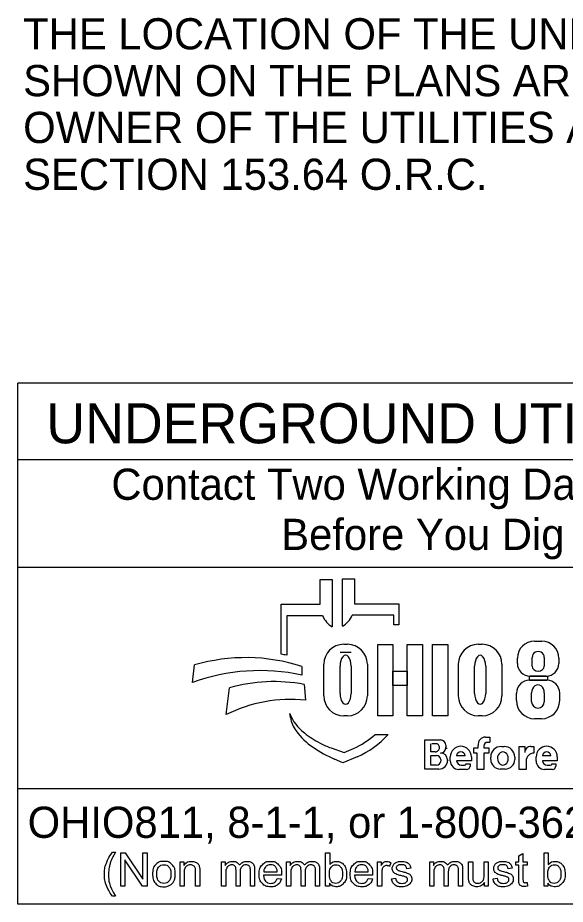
# Model space of a CAD drawing. Extents: x 0 to 34, y -5.8 to 22.
# Drawn here: x 4.602 to 7.056, y 9.052 to 13.029 of the extents above; entities that cross this region are included whole.
import ezdxf

# ---------------------------------------------------------------- set-up
doc = ezdxf.new("R2010")
doc.units = 0
doc.layers.add('SH_Data', color=7, linetype='Continuous')
doc.layers.add('SH_Text', color=7, linetype='Continuous')

msp = doc.modelspace()

# ---------------------------------------------------------------- linework, layer by layer
at = {"layer": 'SH_Data'}
for p, q in [((4.602, 9.0516), (4.602, 11.3891)), ((8.852, 11.3891), (4.602, 11.3891)), ((4.602, 11.0476), (8.852, 11.0476)), ((4.602, 10.5642), (8.852, 10.5642)), ((8.852, 9.5695), (4.602, 9.5695)), ((8.852, 9.0516), (4.602, 9.0516))]:
    msp.add_line(p, q, dxfattribs=at)
at = {"layer": 'SH_Text'}
for p, q in [((5.958, 10.3972), (5.958, 10.5086)), ((5.958, 10.5086), (6.0116, 10.5086)), ((6.0116, 10.5086), (6.0116, 10.2966)), ((6.0573, 10.2989), (6.0573, 10.511)), ((6.0573, 10.511), (6.1109, 10.511)), ((6.1109, 10.511), (6.1109, 10.3995)), ((5.782, 10.1733), (5.782, 10.3972)), ((5.782, 10.3972), (5.958, 10.3972)), ((6.1109, 10.3995), (6.3102, 10.3995)), ((6.3102, 10.3995), (6.3102, 10.3057)), ((5.8073, 10.3457), (5.8073, 10.1689)), ((5.9684, 10.3457), (5.8073, 10.3457)), ((6.2869, 10.348), (6.1005, 10.348)), ((6.2869, 10.3057), (6.2869, 10.348)), ((6.3102, 10.3057), (6.2869, 10.3057)), ((6.9176, 10.232), (6.9503, 10.232)), ((6.063, 10.218), (6.0795, 10.218)), ((6.666, 10.218), (6.6826, 10.218)), ((6.0962, 10.181), (6.0464, 10.181)), ((6.8412, 10.1314), (6.8412, 10.1557)), ((6.9074, 10.12), (6.9074, 10.1593)), ((6.9616, 10.1593), (6.9616, 10.12)), ((7.0266, 10.1557), (7.0266, 10.1314)), ((5.3847, 10.047), (5.3941, 10.1251)), ((5.8753, 10.1186), (5.8753, 10.0798)), ((5.9735, 9.9865), (5.9735, 10.1285)), ((6.0464, 9.9979), (6.0464, 10.1202)), ((6.0962, 10.1202), (6.0962, 9.9979)), ((6.169, 10.1285), (6.169, 9.9865)), ((6.5766, 9.9865), (6.5766, 10.1285)), ((6.6495, 9.9979), (6.6495, 10.1202)), ((6.6993, 10.1202), (6.6993, 9.9979)), ((6.772, 10.1285), (6.772, 9.9865)), ((6.9706, 10.0754), (6.8972, 10.0754)), ((5.5365, 9.9024), (5.5512, 10.0226)), ((5.8853, 10.038), (5.8915, 9.967)), ((6.8954, 10.0571), (6.9728, 10.0571)), ((6.8375, 9.9651), (6.8375, 9.9992)), ((6.905, 9.9592), (6.905, 10.0001)), ((6.9619, 10.0001), (6.9619, 9.9592)), ((7.0306, 9.9992), (7.0306, 9.9651)), ((5.8242, 9.8895), (5.8211, 9.9075)), ((6.0795, 9.897), (6.063, 9.897)), ((6.6826, 9.897), (6.666, 9.897)), ((6.9497, 9.8842), (6.9185, 9.8842)), ((6.2045, 9.8137), (6.2619, 9.8137)), ((6.4258, 9.6579), (6.4258, 9.7886)), ((6.4258, 9.7886), (6.4969, 9.7886)), ((6.6983, 9.8014), (6.7178, 9.8014)), ((6.7178, 9.8014), (6.7178, 9.7784)), ((6.006, 9.7533), (6.0655, 9.7328)), ((6.0655, 9.7328), (6.1065, 9.7506)), ((6.4537, 9.7352), (6.4537, 9.7721)), ((6.4789, 9.7721), (6.4577, 9.7721)), ((6.5207, 9.7649), (6.5207, 9.757)), ((6.6458, 9.7301), (6.6458, 9.753)), ((6.6458, 9.753), (6.6651, 9.753)), ((6.6651, 9.753), (6.6651, 9.7635)), ((6.6912, 9.7615), (6.6912, 9.753)), ((6.6912, 9.753), (6.7127, 9.753)), ((6.7178, 9.778), (6.7077, 9.778)), ((6.7127, 9.753), (6.7127, 9.7301)), ((6.7696, 9.7596), (6.7817, 9.7596)), ((6.8498, 9.6567), (6.8498, 9.7594)), ((6.8498, 9.7594), (6.8744, 9.7594)), ((6.8744, 9.7594), (6.8744, 9.7325)), ((6.9016, 9.7594), (6.9155, 9.7594)), ((6.9155, 9.7594), (6.9155, 9.7297)), ((6.1227, 9.7132), (6.0594, 9.6858)), ((6.4732, 9.7352), (6.4537, 9.7352)), ((6.4537, 9.6757), (6.4537, 9.7186)), ((6.4537, 9.7186), (6.4793, 9.7186)), ((6.5403, 9.6947), (6.5403, 9.7131)), ((6.6069, 9.7171), (6.5684, 9.7171)), ((6.6348, 9.7131), (6.6348, 9.6954)), ((6.6607, 9.7301), (6.6458, 9.7301)), ((6.6607, 9.6567), (6.6607, 9.7301)), ((6.7127, 9.7301), (6.6912, 9.7301)), ((6.6912, 9.7301), (6.6912, 9.6567)), ((6.7218, 9.701), (6.7218, 9.7118)), ((6.8295, 9.7118), (6.8295, 9.701)), ((6.9252, 9.6947), (6.9252, 9.7131)), ((6.9918, 9.7171), (6.9533, 9.7171)), ((7.0198, 9.7131), (7.0198, 9.6954)), ((6.0594, 9.6858), (6.0221, 9.7022)), ((6.479, 9.6757), (6.4537, 9.6757)), ((6.4974, 9.7005), (6.4974, 9.6941)), ((6.5288, 9.6976), (6.5288, 9.6972)), ((6.6348, 9.6954), (6.5684, 9.6954)), ((6.5894, 9.6762), (6.6035, 9.6762)), ((6.612, 9.6818), (6.6289, 9.6818)), ((6.6289, 9.6818), (6.6289, 9.6719)), ((6.8803, 9.6948), (6.8803, 9.6567)), ((7.0198, 9.6954), (6.9533, 9.6954)), ((6.9743, 9.6762), (6.9884, 9.6762)), ((6.997, 9.6818), (7.0138, 9.6818)), ((7.0138, 9.6818), (7.0138, 9.6719)), ((6.4894, 9.6579), (6.4258, 9.6579)), ((6.6137, 9.6567), (6.5783, 9.6567)), ((6.6912, 9.6567), (6.6607, 9.6567)), ((6.7867, 9.6582), (6.7645, 9.6582)), ((6.8803, 9.6567), (6.8498, 9.6567)), ((6.9986, 9.6567), (6.9632, 9.6567))]:
    msp.add_line(p, q, dxfattribs=at)
for points in [[(6.2154, 10.2169), (6.2834, 10.2169), (6.2834, 9.897), (6.2154, 9.897)], [(6.3476, 10.2169), (6.4155, 10.2169), (6.4155, 9.897), (6.3476, 9.897)], [(6.4609, 10.2169), (6.5296, 10.2169), (6.5296, 9.897), (6.4609, 9.897)], [(6.2834, 10.097), (6.3476, 10.097), (6.3476, 10.033), (6.2834, 10.033)], [(6.8951, 10.0754), (6.9768, 10.0754), (6.9768, 10.0569), (6.8951, 10.0569)]]:
    msp.add_lwpolyline(points, close=True, dxfattribs=at)
for points in [[(5.0266, 9.2854), (5.0397, 9.2854)], [(5.0633, 9.1328), (5.0633, 9.2829), (5.0836, 9.2829), (5.1627, 9.165), (5.1627, 9.2829), (5.1816, 9.2829), (5.1816, 9.1328), (5.1613, 9.1328), (5.0823, 9.2507), (5.0823, 9.1328), (5.0633, 9.1328)], [(5.9988, 9.1328), (5.9817, 9.1328), (5.9817, 9.2829), (6.0001, 9.2829), (6.0001, 9.2294)], [(6.8477, 9.1646), (6.8477, 9.2273), (6.8341, 9.2273), (6.8341, 9.2416), (6.8477, 9.2416), (6.8477, 9.2686), (6.8661, 9.2796), (6.8661, 9.2416), (6.8846, 9.2416), (6.8846, 9.2273), (6.8661, 9.2273), (6.8661, 9.1636)], [(6.9778, 9.1328), (6.9608, 9.1328), (6.9608, 9.2829), (6.9792, 9.2829), (6.9792, 9.2294)], [(5.3293, 9.1328), (5.3293, 9.2416), (5.3459, 9.2416), (5.3459, 9.2261)], [(5.5157, 9.1328), (5.5157, 9.2416), (5.5322, 9.2416), (5.5322, 9.2263)], [(5.8071, 9.1328), (5.8071, 9.2416), (5.8235, 9.2416), (5.8235, 9.2263)], [(6.2148, 9.1328), (6.2148, 9.2416), (6.2314, 9.2416), (6.2314, 9.2251)], [(6.2739, 9.2381), (6.2674, 9.2211)], [(6.4481, 9.1328), (6.4481, 9.2416), (6.4645, 9.2416), (6.4645, 9.2263)], [(6.6224, 9.1742), (6.6224, 9.2416), (6.6408, 9.2416), (6.6408, 9.1813)], [(6.6921, 9.1834), (6.6921, 9.2416), (6.7105, 9.2416), (6.7105, 9.1328), (6.694, 9.1328)], [(5.3477, 9.1922), (5.3477, 9.1328), (5.3293, 9.1328)], [(5.4176, 9.1997), (5.4176, 9.1328), (5.3992, 9.1328), (5.3992, 9.1989)], [(5.5341, 9.1892), (5.5341, 9.1328), (5.5157, 9.1328)], [(5.5988, 9.196), (5.5988, 9.1328), (5.5803, 9.1328), (5.5803, 9.2034)], [(5.6632, 9.2075), (5.6632, 9.1328), (5.6448, 9.1328), (5.6448, 9.2013)], [(5.7043, 9.1976), (5.7651, 9.1976)], [(5.8255, 9.1892), (5.8255, 9.1328), (5.8071, 9.1328)], [(5.8901, 9.196), (5.8901, 9.1328), (5.8717, 9.1328), (5.8717, 9.2034)], [(5.9546, 9.2075), (5.9546, 9.1328), (5.9362, 9.1328), (5.9362, 9.2013)], [(6.1123, 9.1976), (6.1731, 9.1976)], [(6.2333, 9.1898), (6.2333, 9.1328), (6.2148, 9.1328)], [(6.3639, 9.2135), (6.3458, 9.2111)], [(6.4665, 9.1892), (6.4665, 9.1328), (6.4481, 9.1328)], [(6.5311, 9.196), (6.5311, 9.1328), (6.5127, 9.1328), (6.5127, 9.2034)], [(6.5956, 9.2075), (6.5956, 9.1328), (6.5772, 9.1328), (6.5772, 9.2013)], [(6.8184, 9.2135), (6.8003, 9.2111)], [(5.7844, 9.1824), (5.7033, 9.1824)], [(5.7649, 9.1679), (5.7839, 9.1655)], [(6.1924, 9.1824), (6.1113, 9.1824)], [(6.1729, 9.1679), (6.1919, 9.1655)], [(6.2774, 9.1653), (6.2956, 9.1681)], [(6.694, 9.1328), (6.694, 9.1488)], [(6.732, 9.1653), (6.7502, 9.1681)], [(6.8846, 9.1492), (6.8872, 9.1329)], [(5.9988, 9.1464), (5.9988, 9.1328)], [(6.9778, 9.1464), (6.9778, 9.1328)], [(5.0397, 9.0886), (5.0266, 9.0886)]]:
    msp.add_lwpolyline(points, dxfattribs=at)
for centre, radius, start, end in [((6.0597, 10.3825), 0.0985, 201.9296, 240.7469), ((6.0092, 10.3848), 0.0985, 299.2531, 338.0704), ((6.9176, 10.1557), 0.0763, 90, 180), ((6.9503, 10.1557), 0.0763, 0, 90), ((6.063, 10.1285), 0.0895, 90, 180), ((6.0795, 10.1285), 0.0895, 0, 90), ((6.666, 10.1285), 0.0895, 90, 180), ((6.6826, 10.1285), 0.0895, 0, 90), ((5.6241, 9.339), 0.8191, 72.1402, 106.3144), ((5.6539, 9.3643), 0.8191, 79.2074, 81.0007), ((6.8972, 10.1314), 0.056, 180, 270), ((6.9706, 10.1314), 0.056, 270, 0), ((5.6872, 9.2079), 0.8919, 77.8238, 109.8274), ((5.7511, 9.3182), 0.7322, 79.44, 105.8467), ((6.8954, 9.9992), 0.0579, 90, 180), ((6.9728, 9.9992), 0.0579, 0, 90), ((6.063, 9.9865), 0.0895, 180, 270), ((6.0795, 9.9865), 0.0895, 270, 0), ((6.666, 9.9865), 0.0895, 180, 270), ((6.6826, 9.9865), 0.0895, 270, 0), ((5.8231, 9.335), 0.6357, 83.8248, 116.8021), ((6.9185, 9.9651), 0.081, 180, 270), ((6.9497, 9.9651), 0.081, 270, 0), ((6.0085, 9.9796), 0.2008, 201.0457, 232.5314), ((5.9655, 9.9136), 0.1433, 189.6817, 216.0884), ((6.0992, 10.0111), 0.3088, 216.0884, 235.7167), ((6.2011, 10.2308), 0.5173, 232.5314, 241.794), ((5.9631, 10.0811), 0.3602, 293.4582, 312.0712), ((5.9631, 10.0811), 0.401, 293.4582, 317.8286), ((6.4969, 9.7649), 0.0238, 0, 90), ((6.6983, 9.7679), 0.0335, 90, 187.5187), ((6.2657, 10.2553), 0.6044, 235.7167, 246.2325), ((6.1159, 10.072), 0.3371, 241.794, 250.9821), ((6.4732, 9.7539), 0.0187, 270, 2.0582), ((6.475, 9.7552), 0.0169, 357.8325, 90), ((6.4965, 9.7542), 0.0243, 270, 6.6529), ((6.5071, 9.7527), 0.0175, 347.4023, 0), ((6.5876, 9.7131), 0.0473, 0, 180), ((6.7077, 9.7615), 0.0165, 90, 180), ((6.7696, 9.7118), 0.0478, 90, 180), ((6.7817, 9.7118), 0.0478, 0, 90), ((6.9013, 9.7325), 0.0269, 89.2449, 180), ((6.9725, 9.7131), 0.0473, 0, 180), ((6.4793, 9.7005), 0.0181, 0, 90), ((6.4967, 9.6978), 0.0321, 4.0748, 90), ((6.4958, 9.6976), 0.033, 0, 11.7502), ((6.5876, 9.7161), 0.0193, 2.9632, 177.0368), ((6.9152, 9.6948), 0.0349, 89.6033, 180), ((6.9725, 9.7161), 0.0193, 2.9632, 177.0368), ((6.479, 9.6941), 0.0184, 270, 0), ((6.4894, 9.6972), 0.0393, 270, 0), ((6.5783, 9.6947), 0.038, 180, 270), ((6.5894, 9.6972), 0.021, 184.827, 270), ((6.6035, 9.6856), 0.00938, 270, 335.9979), ((6.6137, 9.6719), 0.0152, 270, 0), ((6.7645, 9.701), 0.0428, 180, 270), ((6.7867, 9.701), 0.0428, 270, 0), ((6.9632, 9.6947), 0.038, 180, 270), ((6.9743, 9.6972), 0.021, 184.827, 270), ((6.9884, 9.6856), 0.00938, 270, 335.9979), ((6.9986, 9.6719), 0.0152, 270, 0)]:
    msp.add_arc(centre, radius, start, end, dxfattribs=at)
for centre, major_axis, ratio, start_param, end_param in [((6.9345, 10.1593), (0.0271, 0), 0.969373, 0, 3.141593), ((6.0713, 10.1202), (0, 0.0484), 0.514403, 4.712389, 7.853982), ((6.6744, 10.1202), (0, 0.0484), 0.514403, 4.712389, 7.853982), ((6.9345, 10.12), (0.0271, 0), 0.818453, 3.141593, 6.283185), ((6.9335, 10.0001), (0, 0.0358), 0.794529, 4.712389, 7.853982), ((6.0713, 9.9979), (0, 0.0484), 0.514403, 1.570796, 4.712389), ((6.6744, 9.9979), (0, 0.0484), 0.514403, 1.570796, 4.712389), ((6.9335, 9.9592), (0.0284, 0), 0.959837, 3.141593, 6.283185), ((6.7761, 9.7064), (0, 0.029), 0.832186, 4.712389, 7.853982), ((6.7761, 9.7064), (0, 0.0302), 0.797287, 1.570796, 4.712389)]:
    msp.add_ellipse(centre, major_axis=major_axis, ratio=ratio, start_param=start_param, end_param=end_param, dxfattribs=at)
for points in [[(5.0266, 9.0886), (5.0113, 9.1079), (5.0007, 9.1337), (4.9902, 9.1595), (4.9902, 9.1871), (4.9902, 9.2115), (4.9981, 9.2338), (5.0073, 9.2597), (5.0266, 9.2854)], [(5.0397, 9.2854), (5.0274, 9.2641), (5.0234, 9.255), (5.0172, 9.2409), (5.0136, 9.2255), (5.0092, 9.2064), (5.0092, 9.187), (5.0092, 9.1378), (5.0397, 9.0886)], [(5.2058, 9.1872), (5.2058, 9.2174), (5.2226, 9.2319), (5.2366, 9.244), (5.2568, 9.244), (5.2792, 9.244), (5.2934, 9.2293), (5.3077, 9.2146), (5.3077, 9.1887), (5.3077, 9.1677), (5.3014, 9.1557), (5.2951, 9.1437), (5.283, 9.137), (5.271, 9.1304), (5.2568, 9.1304), (5.2339, 9.1304), (5.2199, 9.145), (5.2058, 9.1597), (5.2058, 9.1872)], [(5.2248, 9.1872), (5.2248, 9.1663), (5.2339, 9.1559), (5.243, 9.1455), (5.2568, 9.1455), (5.2705, 9.1455), (5.2796, 9.1559), (5.2887, 9.1664), (5.2887, 9.1878), (5.2887, 9.208), (5.2795, 9.2184), (5.2704, 9.2288), (5.2568, 9.2288), (5.243, 9.2288), (5.2339, 9.2184), (5.2248, 9.2081), (5.2248, 9.1872)], [(5.3459, 9.2261), (5.3579, 9.244), (5.3805, 9.244), (5.3903, 9.244), (5.3985, 9.2405), (5.4068, 9.237), (5.4109, 9.2312), (5.415, 9.2255), (5.4166, 9.2176), (5.4176, 9.2125), (5.4176, 9.1997)], [(5.3992, 9.1989), (5.3992, 9.2102), (5.3971, 9.2158), (5.3949, 9.2213), (5.3894, 9.2247), (5.384, 9.228), (5.3766, 9.228), (5.3648, 9.228), (5.3563, 9.2205), (5.3477, 9.2131), (5.3477, 9.1922)], [(5.5322, 9.2263), (5.5373, 9.2343), (5.5458, 9.2391), (5.5543, 9.244), (5.5652, 9.244), (5.5773, 9.244), (5.585, 9.239), (5.5927, 9.234), (5.5959, 9.2249), (5.6088, 9.244), (5.6296, 9.244), (5.6458, 9.244), (5.6545, 9.2351), (5.6632, 9.2261), (5.6632, 9.2075)], [(5.5803, 9.2034), (5.5803, 9.2157), (5.5758, 9.2219), (5.5713, 9.228), (5.5611, 9.228), (5.5533, 9.228), (5.5467, 9.2239), (5.5401, 9.2198), (5.5371, 9.2119), (5.5341, 9.204), (5.5341, 9.1892)], [(5.6448, 9.2013), (5.6448, 9.2123), (5.643, 9.2172), (5.6412, 9.2221), (5.6365, 9.225), (5.6318, 9.228), (5.6254, 9.228), (5.6139, 9.228), (5.6064, 9.2204), (5.5988, 9.2127), (5.5988, 9.196)], [(5.7839, 9.1655), (5.7794, 9.1488), (5.7672, 9.1396), (5.755, 9.1304), (5.7361, 9.1304), (5.7122, 9.1304), (5.6983, 9.1451), (5.6843, 9.1598), (5.6843, 9.1863), (5.6843, 9.2137), (5.6984, 9.2289), (5.7125, 9.244), (5.7351, 9.244), (5.7569, 9.244), (5.7707, 9.2292), (5.7845, 9.2143), (5.7845, 9.1874), (5.7845, 9.1857), (5.7844, 9.1824)], [(5.7651, 9.1976), (5.7639, 9.2113), (5.7581, 9.2182), (5.7493, 9.2289), (5.7353, 9.2289), (5.7226, 9.2289), (5.7139, 9.2204), (5.7052, 9.2118), (5.7043, 9.1976)], [(5.8235, 9.2263), (5.8287, 9.2343), (5.8372, 9.2391), (5.8457, 9.244), (5.8565, 9.244), (5.8686, 9.244), (5.8764, 9.239), (5.8841, 9.234), (5.8873, 9.2249), (5.9002, 9.244), (5.9209, 9.244), (5.9371, 9.244), (5.9459, 9.2351), (5.9546, 9.2261), (5.9546, 9.2075)], [(5.8717, 9.2034), (5.8717, 9.2157), (5.8672, 9.2219), (5.8627, 9.228), (5.8525, 9.228), (5.8447, 9.228), (5.838, 9.2239), (5.8314, 9.2198), (5.8285, 9.2119), (5.8255, 9.204), (5.8255, 9.1892)], [(5.9362, 9.2013), (5.9362, 9.2123), (5.9344, 9.2172), (5.9326, 9.2221), (5.9279, 9.225), (5.9231, 9.228), (5.9168, 9.228), (5.9053, 9.228), (5.8977, 9.2204), (5.8901, 9.2127), (5.8901, 9.196)], [(5.9985, 9.188), (5.9985, 9.1684), (6.0039, 9.1597), (6.0126, 9.1455), (6.0274, 9.1455), (6.0394, 9.1455), (6.0482, 9.156), (6.057, 9.1665), (6.057, 9.1873), (6.057, 9.2086), (6.0486, 9.2188), (6.0402, 9.2289), (6.0282, 9.2289), (6.0161, 9.2289), (6.0073, 9.2184), (5.9985, 9.2079), (5.9985, 9.188)], [(6.0001, 9.2294), (6.0118, 9.244), (6.0299, 9.244), (6.04, 9.244), (6.0489, 9.24), (6.0579, 9.2359), (6.0637, 9.2286), (6.0695, 9.2213), (6.0727, 9.211), (6.076, 9.2006), (6.076, 9.1888), (6.076, 9.1609), (6.0622, 9.1456), (6.0484, 9.1304), (6.029, 9.1304), (6.0097, 9.1304), (5.9988, 9.1464)], [(6.1919, 9.1655), (6.1874, 9.1488), (6.1752, 9.1396), (6.163, 9.1304), (6.1441, 9.1304), (6.1202, 9.1304), (6.1063, 9.1451), (6.0923, 9.1598), (6.0923, 9.1863), (6.0923, 9.2137), (6.1064, 9.2289), (6.1205, 9.244), (6.1431, 9.244), (6.1649, 9.244), (6.1787, 9.2292), (6.1925, 9.2143), (6.1925, 9.1874), (6.1925, 9.1857), (6.1924, 9.1824)], [(6.1731, 9.1976), (6.1718, 9.2113), (6.1661, 9.2182), (6.1573, 9.2289), (6.1433, 9.2289), (6.1305, 9.2289), (6.1219, 9.2204), (6.1132, 9.2118), (6.1123, 9.1976)], [(6.2314, 9.2251), (6.2378, 9.2367), (6.2432, 9.2403), (6.2485, 9.244), (6.255, 9.244), (6.2643, 9.244), (6.2739, 9.2381)], [(6.3458, 9.2111), (6.3445, 9.2195), (6.3386, 9.2242), (6.3327, 9.2289), (6.322, 9.2289), (6.3093, 9.2289), (6.3038, 9.2247), (6.2984, 9.2205), (6.2984, 9.2149), (6.2984, 9.2113), (6.3006, 9.2084), (6.3029, 9.2054), (6.3077, 9.2035), (6.3105, 9.2024), (6.324, 9.1987), (6.3436, 9.1935), (6.3514, 9.1902), (6.3591, 9.1869), (6.3636, 9.1805), (6.368, 9.1742), (6.368, 9.1648), (6.368, 9.1556), (6.3626, 9.1474), (6.3572, 9.1393), (6.347, 9.1348), (6.3369, 9.1304), (6.324, 9.1304), (6.3028, 9.1304), (6.2917, 9.1392), (6.2805, 9.148), (6.2774, 9.1653)], [(6.2956, 9.1681), (6.2972, 9.1572), (6.3042, 9.1513), (6.3113, 9.1455), (6.3239, 9.1455), (6.3366, 9.1455), (6.3428, 9.1507), (6.349, 9.1558), (6.349, 9.1628), (6.349, 9.1691), (6.3435, 9.1727), (6.3397, 9.1751), (6.3246, 9.1789), (6.3043, 9.184), (6.2965, 9.1878), (6.2886, 9.1915), (6.2846, 9.1981), (6.2805, 9.2047), (6.2805, 9.2127), (6.2805, 9.22), (6.2839, 9.2262), (6.2872, 9.2324), (6.293, 9.2364), (6.2973, 9.2396), (6.3047, 9.2418), (6.3121, 9.244), (6.3207, 9.244), (6.3335, 9.244), (6.3432, 9.2403), (6.3529, 9.2366), (6.3575, 9.2303), (6.3621, 9.224), (6.3639, 9.2135)], [(6.4645, 9.2263), (6.4697, 9.2343), (6.4782, 9.2391), (6.4867, 9.244), (6.4975, 9.244), (6.5096, 9.244), (6.5174, 9.239), (6.5251, 9.234), (6.5283, 9.2249), (6.5412, 9.244), (6.5619, 9.244), (6.5781, 9.244), (6.5869, 9.2351), (6.5956, 9.2261), (6.5956, 9.2075)], [(6.5127, 9.2034), (6.5127, 9.2157), (6.5082, 9.2219), (6.5037, 9.228), (6.4934, 9.228), (6.4857, 9.228), (6.479, 9.2239), (6.4724, 9.2198), (6.4695, 9.2119), (6.4665, 9.204), (6.4665, 9.1892)], [(6.5772, 9.2013), (6.5772, 9.2123), (6.5754, 9.2172), (6.5736, 9.2221), (6.5689, 9.225), (6.5641, 9.228), (6.5578, 9.228), (6.5463, 9.228), (6.5387, 9.2204), (6.5311, 9.2127), (6.5311, 9.196)], [(6.8003, 9.2111), (6.7991, 9.2195), (6.7932, 9.2242), (6.7873, 9.2289), (6.7765, 9.2289), (6.7638, 9.2289), (6.7584, 9.2247), (6.753, 9.2205), (6.753, 9.2149), (6.753, 9.2113), (6.7552, 9.2084), (6.7575, 9.2054), (6.7623, 9.2035), (6.7651, 9.2024), (6.7786, 9.1987), (6.7982, 9.1935), (6.8059, 9.1902), (6.8137, 9.1869), (6.8181, 9.1805), (6.8225, 9.1742), (6.8225, 9.1648), (6.8225, 9.1556), (6.8172, 9.1474), (6.8118, 9.1393), (6.8016, 9.1348), (6.7914, 9.1304), (6.7786, 9.1304), (6.7574, 9.1304), (6.7462, 9.1392), (6.7351, 9.148), (6.732, 9.1653)], [(6.7502, 9.1681), (6.7518, 9.1572), (6.7588, 9.1513), (6.7658, 9.1455), (6.7785, 9.1455), (6.7912, 9.1455), (6.7974, 9.1507), (6.8035, 9.1558), (6.8035, 9.1628), (6.8035, 9.1691), (6.7981, 9.1727), (6.7943, 9.1751), (6.7792, 9.1789), (6.7589, 9.184), (6.7511, 9.1878), (6.7432, 9.1915), (6.7392, 9.1981), (6.7351, 9.2047), (6.7351, 9.2127), (6.7351, 9.22), (6.7384, 9.2262), (6.7418, 9.2324), (6.7475, 9.2364), (6.7518, 9.2396), (6.7593, 9.2418), (6.7667, 9.244), (6.7752, 9.244), (6.788, 9.244), (6.7977, 9.2403), (6.8074, 9.2366), (6.8121, 9.2303), (6.8167, 9.224), (6.8184, 9.2135)], [(6.9776, 9.188), (6.9776, 9.1684), (6.9829, 9.1597), (6.9916, 9.1455), (7.0064, 9.1455), (7.0185, 9.1455), (7.0273, 9.156), (7.0361, 9.1665), (7.0361, 9.1873), (7.0361, 9.2086), (7.0277, 9.2188), (7.0192, 9.2289), (7.0073, 9.2289), (6.9952, 9.2289), (6.9864, 9.2184), (6.9776, 9.2079), (6.9776, 9.188)], [(6.9792, 9.2294), (6.9909, 9.244), (7.009, 9.244), (7.019, 9.244), (7.028, 9.24), (7.037, 9.2359), (7.0428, 9.2286), (7.0485, 9.2213), (7.0518, 9.211), (7.0551, 9.2006), (7.0551, 9.1888), (7.0551, 9.1609), (7.0413, 9.1456), (7.0274, 9.1304), (7.0081, 9.1304), (6.9888, 9.1304), (6.9778, 9.1464)], [(6.2674, 9.2211), (6.2607, 9.225), (6.254, 9.225), (6.248, 9.225), (6.2432, 9.2214), (6.2384, 9.2177), (6.2363, 9.2113), (6.2333, 9.2015), (6.2333, 9.1898)], [(5.7033, 9.1824), (5.7043, 9.1645), (5.7134, 9.155), (5.7225, 9.1455), (5.7362, 9.1455), (5.7463, 9.1455), (5.7535, 9.1508), (5.7607, 9.1562), (5.7649, 9.1679)], [(6.1113, 9.1824), (6.1123, 9.1645), (6.1214, 9.155), (6.1305, 9.1455), (6.1442, 9.1455), (6.1543, 9.1455), (6.1615, 9.1508), (6.1687, 9.1562), (6.1729, 9.1679)], [(6.694, 9.1488), (6.6813, 9.1304), (6.6595, 9.1304), (6.6499, 9.1304), (6.6416, 9.1341), (6.6332, 9.1378), (6.6292, 9.1433), (6.6251, 9.1489), (6.6235, 9.157), (6.6224, 9.1624), (6.6224, 9.1742)], [(6.6408, 9.1813), (6.6408, 9.1669), (6.6419, 9.1618), (6.6437, 9.1546), (6.6493, 9.1504), (6.6549, 9.1463), (6.6632, 9.1463), (6.6715, 9.1463), (6.6788, 9.1505), (6.686, 9.1548), (6.6891, 9.1621), (6.6921, 9.1694), (6.6921, 9.1834)], [(6.8872, 9.1329), (6.8794, 9.1313), (6.8733, 9.1313), (6.8633, 9.1313), (6.8577, 9.1345), (6.8522, 9.1377), (6.85, 9.1428), (6.8477, 9.148), (6.8477, 9.1646)], [(6.8661, 9.1636), (6.8661, 9.1556), (6.8671, 9.1534), (6.8681, 9.1511), (6.8703, 9.1498), (6.8725, 9.1485), (6.8765, 9.1485), (6.8796, 9.1485), (6.8846, 9.1492)]]:
    msp.add_open_spline(points, degree=3, dxfattribs=at)

# ---------------------------------------------------------------- texts
for s, height, p in [('THE LOCATION OF THE UNDERGROUND UTILITIES', 0.14, (4.6262, 12.8866)), ('SHOWN ON THE PLANS ARE OBTAINED FROM THE', 0.14, (4.6262, 12.6766)), ('OWNER OF THE UTILITIES AS REQUIRED BY', 0.14, (4.6262, 12.4666)), ('SECTION 153.64 O.R.C.', 0.14, (4.6262, 12.2566)), ('UNDERGROUND UTILITIES', 0.18, (4.7301, 11.1195)), ('Contact Two Working Days', 0.14, (5.0216, 10.866)), ('Before You Dig', 0.14, (5.7828, 10.641)), ('OHIO811, 8-1-1, or 1-800-362-2764', 0.14, (4.6464, 9.3495))]:
    msp.add_text(s, height=height, dxfattribs=at).set_placement(p)

doc.saveas('drawing.dxf')
